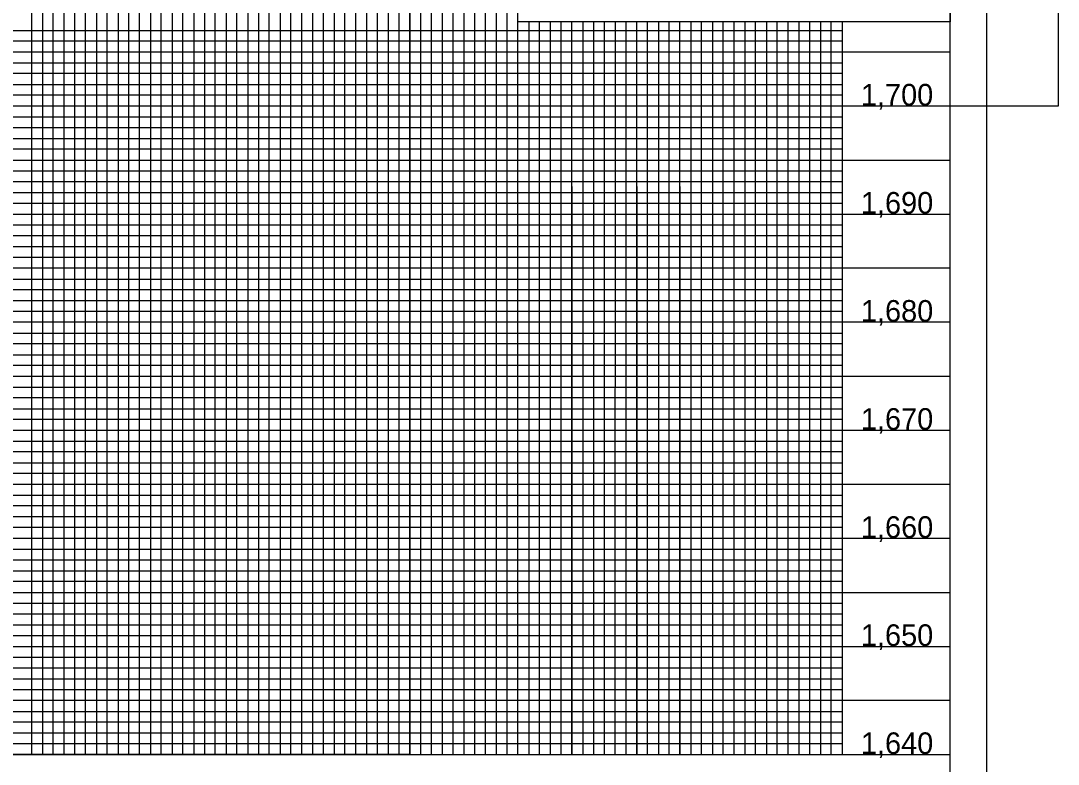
# Model space of a CAD drawing. Extents: x 505569 to 516904, y 436011 to 484484.
# Drawn here: x 506839.1 to 507319.1, y 483679.2 to 484023.2 of the extents above; entities that cross this region are included whole.
import ezdxf

# ---------------------------------------------------------------- set-up
doc = ezdxf.new("R2010")
doc.units = 0
for name, color, linetype in [('COGO Default Curve', 7, 'Continuous'), ('Exist Profile Cell', 7, 'Continuous'), ('Exist Vertical Profile Vertical Axis Label', 7, 'Continuous'), ('Prop Grid Mask', 7, 'Continuous'), ('Prop Vertical Profile Curve Label', 7, 'Continuous'), ('Prop Vertical Profile Grade Label', 7, 'Continuous'), ('Raster_Level_3', 7, 'Continuous'), ('Scratch_Level_2', 7, 'Continuous')]:
    doc.layers.add(name, color=color, linetype=linetype)

msp = doc.modelspace()

# ---------------------------------------------------------------- linework, layer by layer
at = {"layer": 'COGO Default Curve'}
for points in [[(506794.08, 484183.71), (506844.08, 484183.71), (506844.08, 483683.71), (506894.08, 483683.71), (506894.08, 484183.71), (506944.08, 484183.71), (506944.08, 483683.71), (506994.08, 483683.71), (506994.08, 484183.71), (507044.08, 484183.71), (507044.08, 483683.71), (507094.08, 483683.71), (507094.08, 484022.66)], [(507094.08, 483946.51), (507094.08, 483683.71), (507144.08, 483683.71), (507144.08, 484022.66)], [(507144.08, 483946.51), (507144.08, 483683.71), (507194.08, 483683.71), (507194.08, 484022.66)], [(507269.08, 484008.71), (505769.08, 484008.71), (505769.08, 483958.71), (507094.08, 483958.71)], [(507094.08, 483958.71), (507269.08, 483958.71)], [(507269.08, 483908.71), (505769.08, 483908.71), (505769.08, 483858.71), (507269.08, 483858.71)], [(507269.08, 483808.71), (505769.08, 483808.71), (505769.08, 483758.71), (507269.08, 483758.71)], [(507269.08, 483708.71), (505769.08, 483708.71)]]:
    msp.add_lwpolyline(points, dxfattribs=at)
at = {"layer": 'Exist Vertical Profile Vertical Axis Label'}
for points in [[(506119.08, 484483.71), (507319.08, 484483.71), (507319.08, 483983.71), (507319.08, 483983.71), (507319.08, 483983.71), (506119.08, 483983.71)], [(505819.08, 484183.71), (505819.08, 483683.71), (507019.08, 483683.71), (507019.08, 483998.71), (507019.08, 484053.71), (507019.08, 484183.71)], [(505819.08, 484183.71), (507019.08, 484183.71), (507019.08, 483683.71), (507019.08, 483683.71), (507019.08, 483683.71), (505819.08, 483683.71)]]:
    msp.add_lwpolyline(points, close=True, dxfattribs=at)
at = {"layer": 'Prop Grid Mask'}
msp.add_lwpolyline([(505602.08, 483108.71), (507286.08, 483108.71), (507286.08, 484208.71), (505602.08, 484208.71)], close=True, dxfattribs=at)
at = {"layer": 'Prop Vertical Profile Curve Label'}
msp.add_line((505769.08, 483683.71), (507269.08, 483683.71), dxfattribs=at)
msp.add_lwpolyline([(507269.08, 484183.71), (505769.08, 484183.71), (505769.08, 483133.71), (507269.08, 483133.71)], close=True, dxfattribs=at)
at = {"layer": 'Prop Vertical Profile Grade Label'}
for p, q in [((505819.08, 484018.71), (507219.08, 484018.71)), ((507219.08, 483998.71), (505819.08, 483998.71)), ((505819.08, 483993.71), (507219.08, 483993.71)), ((507219.08, 483973.71), (505819.08, 483973.71)), ((505819.08, 483968.71), (507219.08, 483968.71)), ((507219.08, 483948.71), (505819.08, 483948.71)), ((505819.08, 483943.71), (507219.08, 483943.71)), ((507219.08, 483938.71), (505819.08, 483938.71)), ((505819.08, 483928.71), (507219.08, 483928.71)), ((507219.08, 483923.71), (505819.08, 483923.71)), ((505819.08, 483918.71), (507219.08, 483918.71)), ((507219.08, 483913.71), (505819.08, 483913.71)), ((505819.08, 483903.71), (507219.08, 483903.71)), ((507219.08, 483898.71), (505819.08, 483898.71)), ((505819.08, 483893.71), (507219.08, 483893.71)), ((507219.08, 483888.71), (505819.08, 483888.71)), ((505819.08, 483878.71), (507219.08, 483878.71)), ((507219.08, 483873.71), (505819.08, 483873.71)), ((505819.08, 483868.71), (507219.08, 483868.71)), ((507219.08, 483863.71), (505819.08, 483863.71)), ((505819.08, 483853.71), (507219.08, 483853.71)), ((507219.08, 483848.71), (505819.08, 483848.71)), ((505819.08, 483843.71), (507219.08, 483843.71)), ((507219.08, 483838.71), (505819.08, 483838.71)), ((505819.08, 483828.71), (507219.08, 483828.71)), ((507219.08, 483823.71), (505819.08, 483823.71)), ((505819.08, 483818.71), (507219.08, 483818.71)), ((507219.08, 483813.71), (505819.08, 483813.71)), ((505819.08, 483803.71), (507219.08, 483803.71)), ((507219.08, 483798.71), (505819.08, 483798.71)), ((507219.08, 483793.71), (505819.08, 483793.71)), ((507219.08, 483788.71), (505819.08, 483788.71)), ((505819.08, 483778.71), (507219.08, 483778.71)), ((507219.08, 483773.71), (505819.08, 483773.71)), ((505819.08, 483768.71), (507219.08, 483768.71)), ((507219.08, 483763.71), (505819.08, 483763.71)), ((505819.08, 483753.71), (507219.08, 483753.71)), ((507219.08, 483748.71), (505819.08, 483748.71)), ((505819.08, 483743.71), (507219.08, 483743.71)), ((507219.08, 483738.71), (505819.08, 483738.71)), ((505819.08, 483728.71), (507219.08, 483728.71)), ((507219.08, 483723.71), (505819.08, 483723.71)), ((505819.08, 483718.71), (507219.08, 483718.71)), ((507219.08, 483713.71), (505819.08, 483713.71)), ((505819.08, 483703.71), (507219.08, 483703.71)), ((507219.08, 483698.71), (505819.08, 483698.71)), ((505819.08, 483693.71), (507219.08, 483693.71))]:
    msp.add_line(p, q, dxfattribs=at)
for points in [[(506849.08, 484183.71), (506849.08, 483683.71), (506854.08, 483683.71), (506854.08, 484183.71)], [(506859.08, 484183.71), (506859.08, 483683.71), (506864.08, 483683.71), (506864.08, 484183.71)], [(506874.08, 484183.71), (506874.08, 483683.71), (506879.08, 483683.71), (506879.08, 484183.71)], [(506884.08, 484183.71), (506884.08, 483683.71), (506889.08, 483683.71), (506889.08, 484183.71)], [(506899.08, 484183.71), (506899.08, 483683.71), (506904.08, 483683.71), (506904.08, 484183.71)], [(506909.08, 484183.71), (506909.08, 483683.71), (506914.08, 483683.71), (506914.08, 484183.71)], [(506924.08, 484183.71), (506924.08, 483683.71), (506929.08, 483683.71), (506929.08, 484183.71)], [(506934.08, 484183.71), (506934.08, 483683.71), (506939.08, 483683.71), (506939.08, 484183.71)], [(506949.08, 484183.71), (506949.08, 483683.71), (506954.08, 483683.71), (506954.08, 484183.71)], [(506959.08, 484183.71), (506959.08, 483683.71)], [(506959.08, 483683.71), (506964.08, 483683.71), (506964.08, 484183.71)], [(506974.08, 484183.71), (506974.08, 483683.71), (506979.08, 483683.71), (506979.08, 484183.71)], [(506984.08, 484183.71), (506984.08, 483683.71), (506989.08, 483683.71), (506989.08, 484183.71)], [(506999.08, 484183.71), (506999.08, 483683.71), (507004.08, 483683.71), (507004.08, 484183.71)], [(507009.08, 484183.71), (507009.08, 483683.71), (507014.08, 483683.71), (507014.08, 484183.71)], [(507024.08, 484183.71), (507024.08, 483683.71), (507029.08, 483683.71), (507029.08, 484183.71)], [(507034.08, 484183.71), (507034.08, 483683.71), (507039.08, 483683.71), (507039.08, 484183.71)], [(507049.08, 484183.71), (507049.08, 483683.71), (507054.08, 483683.71), (507054.08, 484183.71)], [(507059.08, 484183.71), (507059.08, 483683.71), (507064.08, 483683.71), (507064.08, 484183.71)], [(507074.08, 484022.66), (507074.08, 483683.71), (507079.08, 483683.71), (507079.08, 484022.66)], [(507084.08, 484022.66), (507084.08, 483683.71), (507089.08, 483683.71), (507089.08, 484022.66)], [(507099.08, 484022.66), (507099.08, 483683.71), (507099.08, 483683.71), (507104.08, 483683.71), (507109.08, 483683.71), (507109.08, 484022.66)], [(507104.08, 484022.66), (507104.08, 483683.71)], [(507114.07, 484022.66), (507113.98, 483683.76), (507118.98, 483683.76), (507124.08, 483683.71), (507124.08, 484022.66)], [(507124.08, 483946.51), (507124.08, 483683.71), (507129.08, 483683.71), (507129.08, 484022.66)], [(507134.08, 484022.66), (507134.08, 483683.71), (507139.08, 483683.71), (507139.08, 484022.66)], [(507149.08, 484022.66), (507149.08, 483683.71), (507154.08, 483683.71), (507154.08, 484022.66)], [(507159.08, 484022.66), (507159.08, 483683.71), (507164.08, 483683.71), (507164.08, 484022.66)], [(507174.08, 484022.66), (507174.08, 483683.71), (507179.08, 483683.71), (507179.08, 484022.66)], [(507184.08, 484022.66), (507184.08, 483683.71), (507189.08, 483683.71), (507189.08, 484022.66)], [(507199.08, 484022.66), (507199.08, 483683.71), (507204.08, 483683.71), (507204.08, 484022.66)], [(507209.08, 484022.66), (507209.08, 483683.71), (507214.08, 483683.71), (507214.08, 484022.66)], [(507219.08, 484013.71), (505819.08, 484013.71), (505819.08, 484003.71), (507219.08, 484003.71)], [(507219.08, 483988.71), (505819.08, 483988.71), (505819.08, 483978.71), (507219.08, 483978.71)], [(507219.08, 483963.71), (505819.08, 483963.71), (505819.08, 483953.71), (507219.08, 483953.71)], [(507219.08, 483688.71), (505819.08, 483688.71)]]:
    msp.add_lwpolyline(points, dxfattribs=at)
at = {"layer": 'Raster_Level_3'}
for p, q in [((507069.03, 484022.66), (507069.03, 484046.16)), ((507069.03, 484022.66), (507069.03, 484046.16)), ((507269.07, 484046.15), (507269.07, 484022.65)), ((507269.07, 484046.15), (507269.07, 484022.65)), ((507269.07, 484022.66), (507069.03, 484022.66)), ((507269.07, 484022.66), (507069.03, 484022.66))]:
    msp.add_line(p, q, dxfattribs=at)
at = {"layer": 'Scratch_Level_2'}
for points in [[(506819.08, 483683.71), (506869.08, 483683.71), (506869.08, 484183.71), (506919.08, 484183.71), (506919.08, 483683.71), (506969.08, 483683.71), (506969.08, 484183.71), (507019.08, 484183.71), (507019.08, 483683.71), (507069.08, 483683.71), (507069.08, 484183.71), (507095.38, 484183.71)], [(507219.08, 484022.66), (507219.08, 483683.71), (507269.08, 483683.71), (507269.08, 484033.71)], [(507119.08, 484022.66), (507119.08, 483683.71), (507169.08, 483683.71), (507169.08, 483683.71), (507169.08, 484022.66)], [(507269.08, 483983.71), (505769.08, 483983.71), (505769.08, 483933.71), (507269.08, 483933.71)], [(507269.08, 483883.71), (505769.08, 483883.71), (505769.08, 483833.71), (507269.08, 483833.71)], [(507269.08, 483783.71), (505769.08, 483783.71), (505769.08, 483783.71), (505769.08, 483733.71), (507269.08, 483733.71)]]:
    msp.add_lwpolyline(points, dxfattribs=at)

# ---------------------------------------------------------------- texts
at = {"layer": 'Exist Profile Cell'}
for s, p in [('1,700', (507227.78, 483983.96)), ('1,690', (507227.78, 483933.96)), ('1,680', (507227.78, 483883.96)), ('1,670', (507227.78, 483833.96)), ('1,660', (507227.78, 483783.96)), ('1,650', (507227.78, 483733.96)), ('1,640', (507227.78, 483683.96))]:
    msp.add_text(s, height=10, dxfattribs=at).set_placement(p)

doc.saveas('drawing.dxf')
